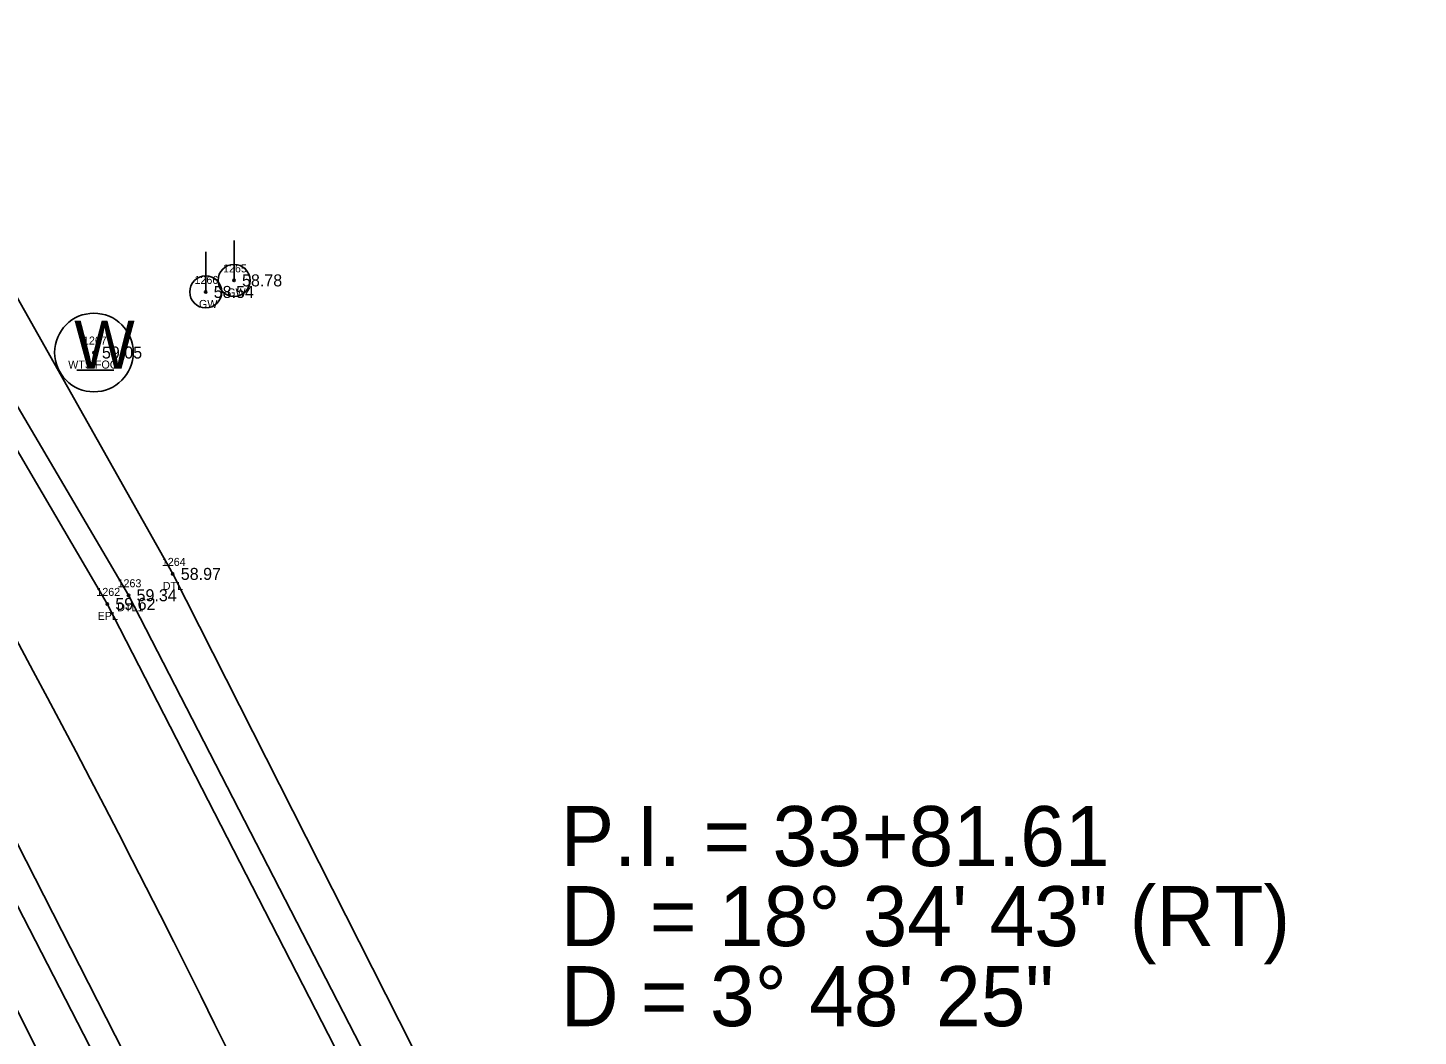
# Model space of a CAD drawing. Extents: x 2396531 to 2397633, y 770203 to 772837.
# Drawn here: x 2397412.4 to 2397586.1, y 770587.8 to 770713.7 of the extents above; entities that cross this region are included whole.
import ezdxf

# ---------------------------------------------------------------- set-up
doc = ezdxf.new("R2010")
doc.units = 0
for name, color, linetype in [('RD_EX_H2O', 7, 'Continuous'), ('RD_EX_H2O_txCode', 7, 'Continuous'), ('RD_EX_Road', 7, 'Continuous'), ('RD_EX_Road_txCode', 7, 'Continuous'), ('RD_EX_TX_H2O_ELEV', 7, 'Continuous'), ('RD_EX_TX_Road_ELEV', 7, 'Continuous'), ('RD_EX_TX_UT_ELEV', 7, 'Continuous'), ('RD_EX_UT', 7, 'Continuous'), ('RD_EX_UT_txCode', 7, 'Continuous'), ('RD_HC_Cl', 7, 'Continuous'), ('RD_HC_Data', 7, 'Continuous'), ('RD_SMD_Locator', 7, 'Continuous')]:
    doc.layers.add(name, color=color, linetype=linetype)

msp = doc.modelspace()

# ---------------------------------------------------------------- linework, layer by layer
at = {"layer": 'RD_EX_H2O'}
for points in [[(2397586.15, 770211.51), (2397567.31, 770287.61), (2397548.79, 770357.79), (2397525.19, 770434.22), (2397495.53, 770510.39), (2397465.51, 770576.5), (2397430.55, 770645.5), (2397380.29, 770734.7), (2397327.01, 770824.44), (2397291.42, 770882.36)], [(2397579.43, 770209.93), (2397561.1, 770285.3), (2397543.19, 770356.19), (2397518.98, 770431.67), (2397489.88, 770507.8), (2397460.56, 770573.86), (2397425.02, 770642.83), (2397373.6, 770730.3), (2397319.08, 770819.92), (2397284.14, 770878.8)], [(2397432.83, 770561.85), (2397399.16, 770627.27), (2397350.75, 770711.42), (2397293.36, 770805.09), (2397257.48, 770863.23)], [(2397432.83, 770561.85), (2397426.86, 770559.56), (2397394.23, 770624.59), (2397345.55, 770708.21), (2397287.31, 770801.51), (2397251.15, 770859.33)]]:
    msp.add_lwpolyline(points, dxfattribs=at)
at = {"layer": 'RD_EX_Road'}
for points in [[(2397576.88, 770209.21), (2397558.85, 770284.47), (2397539.93, 770354.87), (2397515.81, 770430.13), (2397486.97, 770506.75), (2397457.82, 770572.7), (2397422.37, 770641.75), (2397371.16, 770729.12), (2397316.57, 770818.52), (2397280.76, 770876.73)], [(2397553.19, 770205.48), (2397535.12, 770280.96), (2397517, 770349.24), (2397493.4, 770422.78), (2397467.13, 770492.9), (2397441.16, 770551.74), (2397436.66, 770561.67), (2397402.21, 770629.28), (2397353, 770712.83), (2397296, 770806.32), (2397260.16, 770864.73)]]:
    msp.add_lwpolyline(points, dxfattribs=at)
at = {"layer": 'RD_EX_UT'}
for p, q in [((2397434.66, 770680.72), (2397434.66, 770685.72)), ((2397438.2, 770682.16), (2397438.2, 770687.16)), ((2397418.57, 770670.94), (2397423.2, 770670.94))]:
    msp.add_line(p, q, dxfattribs=at)
for centre, radius in [((2397438.2, 770682.16), 2), ((2397434.66, 770680.72), 2), ((2397420.7, 770673.15), 4.91)]:
    msp.add_circle(centre, radius, dxfattribs=at)
at = {"layer": 'RD_HC_Cl'}
msp.add_arc((2396086.26, 769922.93), 1505.07, 12.92958, 31.50817, dxfattribs=at)
at = {"layer": 'RD_SMD_Locator'}
for centre in [(2397438.2, 770682.16), (2397434.66, 770680.72), (2397420.7, 770673.15), (2397430.55, 770645.5), (2397425.02, 770642.83), (2397422.37, 770641.75)]:
    msp.add_circle(centre, 0.15, dxfattribs=at)

# ---------------------------------------------------------------- texts
at = {"layer": 'RD_EX_H2O_txCode'}
for s, p in [('1264', (2397429.18, 770646.5)), ('1263', (2397423.65, 770643.83)), ('DTL', (2397429.3, 770643.5)), ('DTL1', (2397423.61, 770640.83))]:
    msp.add_text(s, height=1, dxfattribs=at).set_placement(p)
at = {"layer": 'RD_EX_Road_txCode'}
for s, p in [('1262', (2397421, 770642.75)), ('EPL', (2397421.16, 770639.75))]:
    msp.add_text(s, height=1, dxfattribs=at).set_placement(p)
at = {"layer": 'RD_EX_TX_H2O_ELEV'}
for s, p in [('58.97', (2397431.55, 770644.75)), ('59.34', (2397426.02, 770642.08))]:
    msp.add_text(s, height=1.5, dxfattribs=at).set_placement(p)
at = {"layer": 'RD_EX_TX_Road_ELEV'}
msp.add_text('59.62', height=1.5, dxfattribs=at).set_placement((2397423.37, 770641))
at = {"layer": 'RD_EX_TX_UT_ELEV'}
for s, p in [('58.78', (2397439.2, 770681.41)), ('58.54', (2397435.66, 770679.97)), ('59.05', (2397421.7, 770672.4))]:
    msp.add_text(s, height=1.5, dxfattribs=at).set_placement(p)
at = {"layer": 'RD_EX_UT'}
msp.add_text('W', height=6, dxfattribs=at).set_placement((2397418.23, 770671.15))
at = {"layer": 'RD_EX_UT_txCode'}
for s, p in [('1265', (2397436.83, 770683.16)), ('1266', (2397433.26, 770681.72)), ('GW', (2397437.35, 770680.16)), ('GW', (2397433.82, 770678.72)), ('1267', (2397419.33, 770674.15)), ('WTS FOC', (2397417.48, 770671.15))]:
    msp.add_text(s, height=1, dxfattribs=at).set_placement(p)
at = {"layer": 'RD_HC_Data'}
for s, p in [('P.I. = 33+81.61', (2397479, 770609)), ('D', (2397479, 770599)), ('    = 18%%d 34\' 43" (RT)', (2397479, 770599)), ('D = 3%%d 48\' 25"', (2397479, 770589))]:
    msp.add_text(s, height=7.5, dxfattribs=at).set_placement(p)

doc.saveas('drawing.dxf')
